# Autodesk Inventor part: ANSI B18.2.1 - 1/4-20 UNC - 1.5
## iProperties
Comments: To add or edit properties for Autodesk Inventor files, use iProperties.
Created: 2005-06
Part Number: ANSI B18.2.1 - 1/4-20 UNC - 1.5
Vendor: Autodesk Inc.
Document SubType Name: Modeling
Designer: John Blackburn
Material: Default
Description: Hex Cap Screw
Standard: ANSI B18.2.1
Size Designation: 1/4-20 UNC - 1.5
Alert: To add or edit properties for Autodesk Inventor files, use iProperties.
Control State: 0
Master: False
Checked Out: False
Shininess: 64.0
Length Units: 11272
Angle Units: 11279
Time Units: 11290
Mass Units: 11286
Length Display Precision: 3
Angle Display Precision: 2
Compacted: True
EGR: 3
Classification: un/spsc 31161513
Density: 0.0
Volumn: 0.0
Area: 0.0
PropertySet Name: Model Information
Author: John Blackburn
Revision Number: 8
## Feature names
1. Body [Revolution]
2. Head [Extrusion]
3. Chamfer1 [Revolution]
4. Chamfer2
